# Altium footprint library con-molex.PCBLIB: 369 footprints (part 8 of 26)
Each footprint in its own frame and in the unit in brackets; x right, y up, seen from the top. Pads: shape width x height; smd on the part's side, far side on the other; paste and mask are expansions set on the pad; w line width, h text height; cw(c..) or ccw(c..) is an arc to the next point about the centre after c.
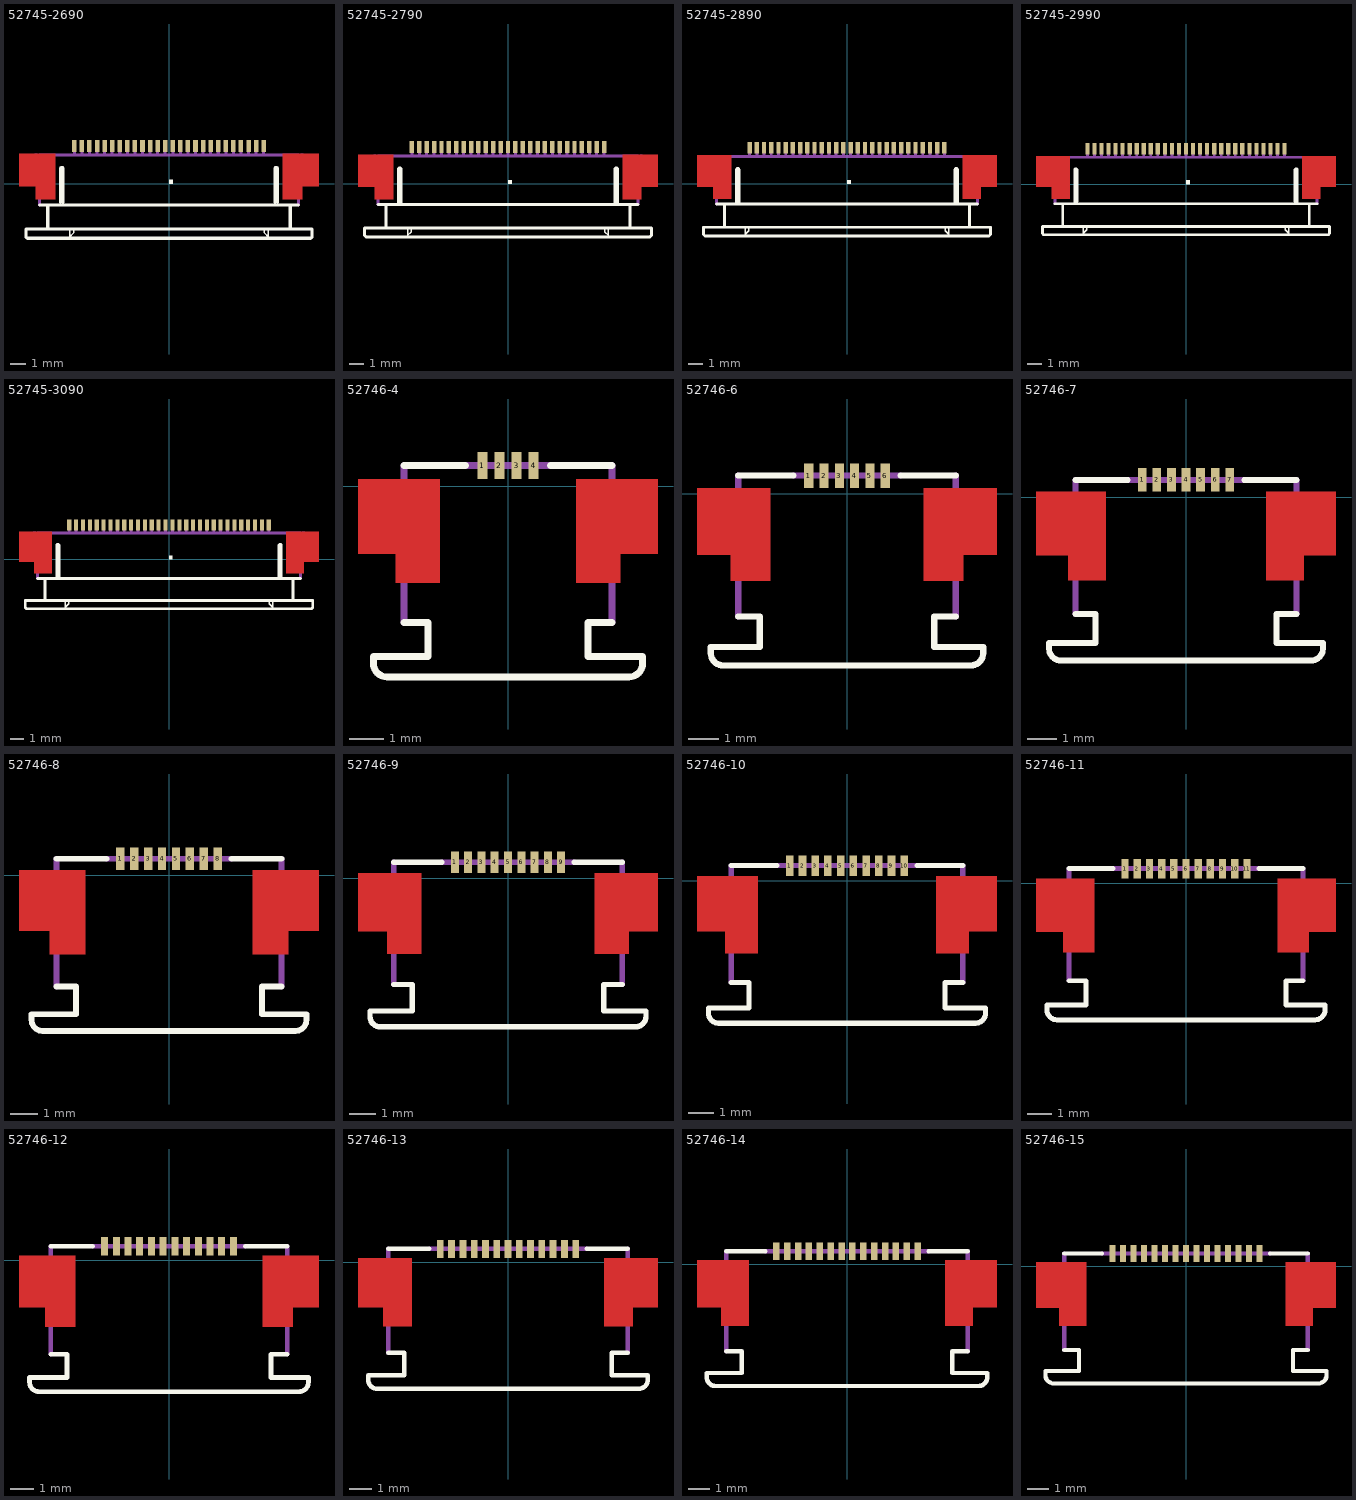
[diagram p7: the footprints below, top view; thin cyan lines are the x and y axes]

## 52745-2690 [mil]
pads (26):
  rect 11.81x31.5 smd: 1(-246.06,98.43) 2(-226.38,98.43) 3(-206.69,98.43) 4(-187.01,98.43) 5(-167.32,98.43) 6(-147.64,98.43) 7(-127.95,98.43) 8(-108.27,98.43) 9(-88.58,98.43) 10(-68.9,98.43) 11(-49.21,98.43) 12(-29.53,98.43) 13(-9.84,98.43) 14(9.84,98.43) 15(29.53,98.43) 16(49.21,98.43) 17(68.9,98.43) 18(88.58,98.43) 19(108.27,98.43) 20(127.95,98.43) 21(147.64,98.43) 22(167.32,98.43) 23(187.01,98.43) 24(206.69,98.43) 25(226.38,98.43) 26(246.06,98.43)
Top Layer:
  rectangle: -389.76,-7.87 -295.28,78.74
  rectangle: -346.46,-41.34 -295.28,-7.87
  rectangle: 295.28,-41.34 346.46,-7.87
  rectangle: 295.28,-7.87 389.76,78.74
Top Overlay:
  region: 0,0 10,0 10,10 0,10
  lines w4: -257.87,-122.05 -257.87,-137.8 -248.03,-127.95 -248.03,-122.05 ; 248.03,-122.05 248.03,-127.95 257.87,-137.8 257.87,-122.05
  lines w8: -336.61,-55.12 336.61,-55.12 ; -314.96,-114.17 -314.96,-59.06 ; -281.5,-49.21 -281.5,39.37 cw(c-278.55,39.37) -275.59,39.37 -275.59,-49.21 ; 275.59,-49.21 275.59,39.37 cw(c278.55,39.37) 281.5,39.37 281.5,-49.21 ; 314.96,-114.17 314.96,-59.06 ; -372.05,-137.8 -372.05,-118.11 372.05,-118.11 372.05,-137.8 368.11,-141.73 -368.11,-141.73 -372.05,-137.8
Top Paste:
  region: 381.89,72.83 303.15,72.83 303.15,-1.97 381.89,-1.97
  rectangle: -381.89,-1.97 -303.15,72.83
Top Solder:
  region: 389.76,78.74 344.49,78.74 344.49,-7.87 389.76,-7.87
  region: 346.46,78.74 295.28,78.74 295.28,-41.34 346.46,-41.34
  rectangle: -389.76,-7.87 -344.49,78.74
  rectangle: -346.46,-41.34 -295.28,78.74
Mechanical 16:
  rectangle: -250,78.74 -242.13,106.3
  rectangle: -230.32,78.74 -222.44,106.3
  rectangle: -210.63,78.74 -202.76,106.3
  rectangle: -190.94,78.74 -183.07,106.3
  rectangle: -171.26,78.74 -163.39,106.3
  rectangle: -151.57,78.74 -143.7,106.3
  rectangle: -131.89,78.74 -124.02,106.3
  rectangle: -112.2,78.74 -104.33,106.3
  rectangle: -92.52,78.74 -84.65,106.3
  rectangle: -72.83,78.74 -64.96,106.3
  rectangle: -53.15,78.74 -45.28,106.3
  rectangle: -33.46,78.74 -25.59,106.3
  rectangle: -13.78,78.74 -5.91,106.3
  rectangle: 5.91,78.74 13.78,106.3
  rectangle: 25.59,78.74 33.46,106.3
  rectangle: 45.28,78.74 53.15,106.3
  rectangle: 64.96,78.74 72.83,106.3
  rectangle: 84.65,78.74 92.52,106.3
  rectangle: 104.33,78.74 112.2,106.3
  rectangle: 124.02,78.74 131.89,106.3
  rectangle: 143.7,78.74 151.57,106.3
  rectangle: 163.39,78.74 171.26,106.3
  rectangle: 183.07,78.74 190.94,106.3
  rectangle: 202.76,78.74 210.63,106.3
  rectangle: 222.44,78.74 230.32,106.3
  rectangle: 242.13,78.74 250,106.3
  lines w4: -342.52,74.8 -342.52,27.56 -372.05,27.56 -372.05,35.43 -350.39,35.43 -348.43,37.4 -348.43,57.09 -372.05,57.09 -372.05,64.96 -348.43,64.96 -348.43,76.77 -342.52,76.77 ; 342.52,74.8 342.52,27.56 372.05,27.56 372.05,35.43 350.39,35.43 348.43,37.4 348.43,57.09 372.05,57.09 372.05,64.96 348.43,64.96 348.43,76.77 342.52,76.77
  lines w8: -336.61,-55.12 -336.61,74.8 336.61,74.8 336.61,-55.12

## 52745-2790 [mil]
pads (27):
  rect 11.81x31.5 smd: 1(-255.91,98.43) 2(-236.22,98.43) 3(-216.54,98.43) 4(-196.85,98.43) 5(-177.17,98.43) 6(-157.48,98.43) 7(-137.8,98.43) 8(-118.11,98.43) 9(-98.43,98.43) 10(-78.74,98.43) 11(-59.06,98.43) 12(-39.37,98.43) 13(-19.69,98.43) 14(0,98.43) 15(19.69,98.43) 16(39.37,98.43) 17(59.06,98.43) 18(78.74,98.43) 19(98.43,98.43) 20(118.11,98.43) 21(137.8,98.43) 22(157.48,98.43) 23(177.17,98.43) 24(196.85,98.43) 25(216.54,98.43) 26(236.22,98.43) 27(255.91,98.43)
Top Layer:
  rectangle: -399.61,-7.87 -305.12,78.74
  rectangle: -356.3,-41.34 -305.12,-7.87
  rectangle: 305.12,-41.34 356.3,-7.87
  rectangle: 305.12,-7.87 399.61,78.74
Top Overlay:
  region: 0,0 10,0 10,10 0,10
  lines w4: -267.72,-122.05 -267.72,-137.8 -257.87,-127.95 -257.87,-122.05 ; 257.87,-122.05 257.87,-127.95 267.72,-137.8 267.72,-122.05
  lines w8: -346.46,-55.12 346.46,-55.12 ; -324.8,-114.17 -324.8,-59.06 ; -291.34,-49.21 -291.34,39.37 cw(c-288.38,39.37) -285.43,39.37 -285.43,-49.21 ; 285.43,-49.21 285.43,39.37 cw(c288.38,39.37) 291.34,39.37 291.34,-49.21 ; 324.8,-114.17 324.8,-59.06 ; -381.89,-137.8 -381.89,-118.11 381.89,-118.11 381.89,-137.8 377.95,-141.73 -377.95,-141.73 -381.89,-137.8
Top Paste:
  region: 391.73,72.83 312.99,72.83 312.99,-1.97 391.73,-1.97
  rectangle: -391.73,-1.97 -312.99,72.83
Top Solder:
  region: 399.61,78.74 354.33,78.74 354.33,-7.87 399.61,-7.87
  region: 356.3,78.74 305.12,78.74 305.12,-41.34 356.3,-41.34
  rectangle: -399.61,-7.87 -354.33,78.74
  rectangle: -356.3,-41.34 -305.12,78.74
Mechanical 16:
  rectangle: -259.84,78.74 -251.97,106.3
  rectangle: -240.16,78.74 -232.28,106.3
  rectangle: -220.47,78.74 -212.6,106.3
  rectangle: -200.79,78.74 -192.91,106.3
  rectangle: -181.1,78.74 -173.23,106.3
  rectangle: -161.42,78.74 -153.54,106.3
  rectangle: -141.73,78.74 -133.86,106.3
  rectangle: -122.05,78.74 -114.17,106.3
  rectangle: -102.36,78.74 -94.49,106.3
  rectangle: -82.68,78.74 -74.8,106.3
  rectangle: -62.99,78.74 -55.12,106.3
  rectangle: -43.31,78.74 -35.43,106.3
  rectangle: -23.62,78.74 -15.75,106.3
  rectangle: -3.94,78.74 3.94,106.3
  rectangle: 15.75,78.74 23.62,106.3
  rectangle: 35.43,78.74 43.31,106.3
  rectangle: 55.12,78.74 62.99,106.3
  rectangle: 74.8,78.74 82.68,106.3
  rectangle: 94.49,78.74 102.36,106.3
  rectangle: 114.17,78.74 122.05,106.3
  rectangle: 133.86,78.74 141.73,106.3
  rectangle: 153.54,78.74 161.42,106.3
  rectangle: 173.23,78.74 181.1,106.3
  rectangle: 192.91,78.74 200.79,106.3
  rectangle: 212.6,78.74 220.47,106.3
  rectangle: 232.28,78.74 240.16,106.3
  rectangle: 251.97,78.74 259.84,106.3
  lines w4: -352.36,74.8 -352.36,27.56 -381.89,27.56 -381.89,35.43 -360.24,35.43 -358.27,37.4 -358.27,57.09 -381.89,57.09 -381.89,64.96 -358.27,64.96 -358.27,76.77 -352.36,76.77 ; 352.36,74.8 352.36,27.56 381.89,27.56 381.89,35.43 360.24,35.43 358.27,37.4 358.27,57.09 381.89,57.09 381.89,64.96 358.27,64.96 358.27,76.77 352.36,76.77
  lines w8: -346.46,-55.12 -346.46,74.8 346.46,74.8 346.46,-55.12

## 52745-2890 [mil]
pads (28):
  rect 11.81x31.5 smd: 1(-265.75,98.43) 2(-246.06,98.43) 3(-226.38,98.43) 4(-206.69,98.43) 5(-187.01,98.43) 6(-167.32,98.43) 7(-147.64,98.43) 8(-127.95,98.43) 9(-108.27,98.43) 10(-88.58,98.43) 11(-68.9,98.43) 12(-49.21,98.43) 13(-29.53,98.43) 14(-9.84,98.43) 15(9.84,98.43) 16(29.53,98.43) 17(49.21,98.43) 18(68.9,98.43) 19(88.58,98.43) 20(108.27,98.43) 21(127.95,98.43) 22(147.64,98.43) 23(167.32,98.43) 24(187.01,98.43) 25(206.69,98.43) 26(226.38,98.43) 27(246.06,98.43) 28(265.75,98.43)
Top Layer:
  rectangle: -409.45,-7.87 -314.96,78.74
  rectangle: -366.14,-41.34 -314.96,-7.87
  rectangle: 314.96,-41.34 366.14,-7.87
  rectangle: 314.96,-7.87 409.45,78.74
Top Overlay:
  region: 0,0 10,0 10,10 0,10
  lines w4: -277.56,-122.05 -277.56,-137.8 -267.72,-127.95 -267.72,-122.05 ; 267.72,-122.05 267.72,-127.95 277.56,-137.8 277.56,-122.05
  lines w8: -356.3,-55.12 356.3,-55.12 ; -334.65,-114.17 -334.65,-59.06 ; -301.18,-49.21 -301.18,39.37 cw(c-298.23,39.37) -295.28,39.37 -295.28,-49.21 ; 295.28,-49.21 295.28,39.37 cw(c298.23,39.37) 301.18,39.37 301.18,-49.21 ; 334.65,-114.17 334.65,-59.06 ; -391.73,-137.8 -391.73,-118.11 391.73,-118.11 391.73,-137.8 387.8,-141.73 -387.8,-141.73 -391.73,-137.8
Top Paste:
  region: 401.57,72.83 322.83,72.83 322.83,-1.97 401.57,-1.97
  rectangle: -401.57,-1.97 -322.83,72.83
Top Solder:
  region: 409.45,78.74 364.17,78.74 364.17,-7.87 409.45,-7.87
  region: 366.14,78.74 314.96,78.74 314.96,-41.34 366.14,-41.34
  rectangle: -409.45,-7.87 -364.17,78.74
  rectangle: -366.14,-41.34 -314.96,78.74
Mechanical 16:
  rectangle: -269.69,78.74 -261.81,106.3
  rectangle: -250,78.74 -242.13,106.3
  rectangle: -230.32,78.74 -222.44,106.3
  rectangle: -210.63,78.74 -202.76,106.3
  rectangle: -190.94,78.74 -183.07,106.3
  rectangle: -171.26,78.74 -163.39,106.3
  rectangle: -151.57,78.74 -143.7,106.3
  rectangle: -131.89,78.74 -124.02,106.3
  rectangle: -112.2,78.74 -104.33,106.3
  rectangle: -92.52,78.74 -84.65,106.3
  rectangle: -72.83,78.74 -64.96,106.3
  rectangle: -53.15,78.74 -45.28,106.3
  rectangle: -33.46,78.74 -25.59,106.3
  rectangle: -13.78,78.74 -5.91,106.3
  rectangle: 5.91,78.74 13.78,106.3
  rectangle: 25.59,78.74 33.46,106.3
  rectangle: 45.28,78.74 53.15,106.3
  rectangle: 64.96,78.74 72.83,106.3
  rectangle: 84.65,78.74 92.52,106.3
  rectangle: 104.33,78.74 112.2,106.3
  rectangle: 124.02,78.74 131.89,106.3
  rectangle: 143.7,78.74 151.57,106.3
  rectangle: 163.39,78.74 171.26,106.3
  rectangle: 183.07,78.74 190.94,106.3
  rectangle: 202.76,78.74 210.63,106.3
  rectangle: 222.44,78.74 230.32,106.3
  rectangle: 242.13,78.74 250,106.3
  rectangle: 261.81,78.74 269.69,106.3
  lines w4: -362.2,74.8 -362.2,27.56 -391.73,27.56 -391.73,35.43 -370.08,35.43 -368.11,37.4 -368.11,57.09 -391.73,57.09 -391.73,64.96 -368.11,64.96 -368.11,76.77 -362.2,76.77 ; 362.2,74.8 362.2,27.56 391.73,27.56 391.73,35.43 370.08,35.43 368.11,37.4 368.11,57.09 391.73,57.09 391.73,64.96 368.11,64.96 368.11,76.77 362.2,76.77
  lines w8: -356.3,-55.12 -356.3,74.8 356.3,74.8 356.3,-55.12

## 52745-2990 [mil]
pads (29):
  rect 11.81x31.5 smd: 1(-275.59,98.43) 2(-255.91,98.43) 3(-236.22,98.43) 4(-216.54,98.43) 5(-196.85,98.43) 6(-177.17,98.43) 7(-157.48,98.43) 8(-137.8,98.43) 9(-118.11,98.43) 10(-98.43,98.43) 11(-78.74,98.43) 12(-59.06,98.43) 13(-39.37,98.43) 14(-19.69,98.43) 15(0,98.43) 16(19.69,98.43) 17(39.37,98.43) 18(59.06,98.43) 19(78.74,98.43) 20(98.43,98.43) 21(118.11,98.43) 22(137.8,98.43) 23(157.48,98.43) 24(177.17,98.43) 25(196.85,98.43) 26(216.54,98.43) 27(236.22,98.43) 28(255.91,98.43) 29(275.59,98.43)
Top Layer:
  rectangle: -419.29,-7.87 -324.8,78.74
  rectangle: -375.98,-41.34 -324.8,-7.87
  rectangle: 324.8,-41.34 375.98,-7.87
  rectangle: 324.8,-7.87 419.29,78.74
Top Overlay:
  region: 0,0 10,0 10,10 0,10
  lines w4: -287.4,-122.05 -287.4,-137.8 -277.56,-127.95 -277.56,-122.05 ; 277.56,-122.05 277.56,-127.95 287.4,-137.8 287.4,-122.05
  lines w8: -366.14,-55.12 366.14,-55.12 ; -344.49,-114.17 -344.49,-59.06 ; -311.02,-49.21 -311.02,39.37 cw(c-308.07,39.37) -305.12,39.37 -305.12,-49.21 ; 305.12,-49.21 305.12,39.37 cw(c308.07,39.37) 311.02,39.37 311.02,-49.21 ; 344.49,-114.17 344.49,-59.06 ; -401.57,-137.8 -401.57,-118.11 401.57,-118.11 401.57,-137.8 397.64,-141.73 -397.64,-141.73 -401.57,-137.8
Top Paste:
  region: 411.42,72.83 332.68,72.83 332.68,-1.97 411.42,-1.97
  rectangle: -411.42,-1.97 -332.68,72.83
Top Solder:
  region: 419.29,78.74 374.02,78.74 374.02,-7.87 419.29,-7.87
  region: 375.98,78.74 324.8,78.74 324.8,-41.34 375.98,-41.34
  rectangle: -419.29,-7.87 -374.02,78.74
  rectangle: -375.98,-41.34 -324.8,78.74
Mechanical 16:
  rectangle: -279.53,78.74 -271.65,106.3
  rectangle: -259.84,78.74 -251.97,106.3
  rectangle: -240.16,78.74 -232.28,106.3
  rectangle: -220.47,78.74 -212.6,106.3
  rectangle: -200.79,78.74 -192.91,106.3
  rectangle: -181.1,78.74 -173.23,106.3
  rectangle: -161.42,78.74 -153.54,106.3
  rectangle: -141.73,78.74 -133.86,106.3
  rectangle: -122.05,78.74 -114.17,106.3
  rectangle: -102.36,78.74 -94.49,106.3
  rectangle: -82.68,78.74 -74.8,106.3
  rectangle: -62.99,78.74 -55.12,106.3
  rectangle: -43.31,78.74 -35.43,106.3
  rectangle: -23.62,78.74 -15.75,106.3
  rectangle: -3.94,78.74 3.94,106.3
  rectangle: 15.75,78.74 23.62,106.3
  rectangle: 35.43,78.74 43.31,106.3
  rectangle: 55.12,78.74 62.99,106.3
  rectangle: 74.8,78.74 82.68,106.3
  rectangle: 94.49,78.74 102.36,106.3
  rectangle: 114.17,78.74 122.05,106.3
  rectangle: 133.86,78.74 141.73,106.3
  rectangle: 153.54,78.74 161.42,106.3
  rectangle: 173.23,78.74 181.1,106.3
  rectangle: 192.91,78.74 200.79,106.3
  rectangle: 212.6,78.74 220.47,106.3
  rectangle: 232.28,78.74 240.16,106.3
  rectangle: 251.97,78.74 259.84,106.3
  rectangle: 271.65,78.74 279.53,106.3
  lines w4: -372.05,74.8 -372.05,27.56 -401.57,27.56 -401.57,35.43 -379.92,35.43 -377.95,37.4 -377.95,57.09 -401.57,57.09 -401.57,64.96 -377.95,64.96 -377.95,76.77 -372.05,76.77 ; 372.05,74.8 372.05,27.56 401.57,27.56 401.57,35.43 379.92,35.43 377.95,37.4 377.95,57.09 401.57,57.09 401.57,64.96 377.95,64.96 377.95,76.77 372.05,76.77
  lines w8: -366.14,-55.12 -366.14,74.8 366.14,74.8 366.14,-55.12

## 52745-3090 [mil]
pads (30):
  rect 11.81x31.5 smd: 1(-285.43,98.43) 2(-265.75,98.43) 3(-246.06,98.43) 4(-226.38,98.43) 5(-206.69,98.43) 6(-187.01,98.43) 7(-167.32,98.43) 8(-147.64,98.43) 9(-127.95,98.43) 10(-108.27,98.43) 11(-88.58,98.43) 12(-68.9,98.43) 13(-49.21,98.43) 14(-29.53,98.43) 15(-9.84,98.43) 16(9.84,98.43) 17(29.53,98.43) 18(49.21,98.43) 19(68.9,98.43) 20(88.58,98.43) 21(108.27,98.43) 22(127.95,98.43) 23(147.64,98.43) 24(167.32,98.43) 25(187.01,98.43) 26(206.69,98.43) 27(226.38,98.43) 28(246.06,98.43) 29(265.75,98.43) 30(285.43,98.43)
Top Layer:
  rectangle: -429.13,-7.87 -334.65,78.74
  rectangle: -385.83,-41.34 -334.65,-7.87
  rectangle: 334.65,-41.34 385.83,-7.87
  rectangle: 334.65,-7.87 429.13,78.74
Top Overlay:
  region: 0,0 10,0 10,10 0,10
  lines w4: -297.24,-122.05 -297.24,-137.8 -287.4,-127.95 -287.4,-122.05 ; 287.4,-122.05 287.4,-127.95 297.24,-137.8 297.24,-122.05
  lines w8: -375.98,-55.12 375.98,-55.12 ; -354.33,-114.17 -354.33,-59.06 ; -320.87,-49.21 -320.87,39.37 cw(c-317.92,39.37) -314.96,39.37 -314.96,-49.21 ; 314.96,-49.21 314.96,39.37 cw(c317.92,39.37) 320.87,39.37 320.87,-49.21 ; 354.33,-114.17 354.33,-59.06 ; -411.42,-137.8 -411.42,-118.11 411.42,-118.11 411.42,-137.8 407.48,-141.73 -407.48,-141.73 -411.42,-137.8
Top Paste:
  region: 421.26,72.83 342.52,72.83 342.52,-1.97 421.26,-1.97
  rectangle: -421.26,-1.97 -342.52,72.83
Top Solder:
  region: 429.13,78.74 383.86,78.74 383.86,-7.87 429.13,-7.87
  region: 385.83,78.74 334.65,78.74 334.65,-41.34 385.83,-41.34
  rectangle: -429.13,-7.87 -383.86,78.74
  rectangle: -385.83,-41.34 -334.65,78.74
Mechanical 16:
  rectangle: -289.37,78.74 -281.5,106.3
  rectangle: -269.69,78.74 -261.81,106.3
  rectangle: -250,78.74 -242.13,106.3
  rectangle: -230.32,78.74 -222.44,106.3
  rectangle: -210.63,78.74 -202.76,106.3
  rectangle: -190.94,78.74 -183.07,106.3
  rectangle: -171.26,78.74 -163.39,106.3
  rectangle: -151.57,78.74 -143.7,106.3
  rectangle: -131.89,78.74 -124.02,106.3
  rectangle: -112.2,78.74 -104.33,106.3
  rectangle: -92.52,78.74 -84.65,106.3
  rectangle: -72.83,78.74 -64.96,106.3
  rectangle: -53.15,78.74 -45.28,106.3
  rectangle: -33.46,78.74 -25.59,106.3
  rectangle: -13.78,78.74 -5.91,106.3
  rectangle: 5.91,78.74 13.78,106.3
  rectangle: 25.59,78.74 33.46,106.3
  rectangle: 45.28,78.74 53.15,106.3
  rectangle: 64.96,78.74 72.83,106.3
  rectangle: 84.65,78.74 92.52,106.3
  rectangle: 104.33,78.74 112.2,106.3
  rectangle: 124.02,78.74 131.89,106.3
  rectangle: 143.7,78.74 151.57,106.3
  rectangle: 163.39,78.74 171.26,106.3
  rectangle: 183.07,78.74 190.94,106.3
  rectangle: 202.76,78.74 210.63,106.3
  rectangle: 222.44,78.74 230.32,106.3
  rectangle: 242.13,78.74 250,106.3
  rectangle: 261.81,78.74 269.69,106.3
  rectangle: 281.5,78.74 289.37,106.3
  lines w4: -381.89,74.8 -381.89,27.56 -411.42,27.56 -411.42,35.43 -389.76,35.43 -387.8,37.4 -387.8,57.09 -411.42,57.09 -411.42,64.96 -387.8,64.96 -387.8,76.77 -381.89,76.77 ; 381.89,74.8 381.89,27.56 411.42,27.56 411.42,35.43 389.76,35.43 387.8,37.4 387.8,57.09 411.42,57.09 411.42,64.96 387.8,64.96 387.8,76.77 381.89,76.77
  lines w8: -375.98,-55.12 -375.98,74.8 375.98,74.8 375.98,-55.12

## 52746-4 [mil]
pads (4):
  rect 11.81x31.5 smd: 1(-29.53,23.62) 2(-9.84,23.62) 3(9.84,23.62) 4(29.53,23.62)
Top Layer:
  rectangle: -173.23,-78.74 -78.74,7.87
  rectangle: -129.92,-112.2 -78.74,-78.74
  rectangle: 78.74,-78.74 173.23,7.87
  rectangle: 78.74,-112.2 129.92,-78.74
Top Overlay:
  lines w8: -120.08,-157.48 -92.52,-157.48 -92.52,-196.85 -155.51,-196.85 -155.51,-204.72 ccw(c-139.76,-204.72) -139.76,-220.47 139.76,-220.47 ccw(c139.76,-204.72) 155.51,-204.72 155.51,-196.85 92.52,-196.85 92.52,-157.48 120.08,-157.48 ; -120.08,23.62 -49.21,23.62 ; 49.21,23.62 120.08,23.62
Top Paste:
  rectangle: -168.31,-74.8 -82.68,2.95
  rectangle: -125.98,-108.27 -82.68,-74.8
  rectangle: 82.68,-74.8 168.31,2.95
  rectangle: 82.68,-108.27 125.98,-74.8
Top Solder:
  rectangle: -173.23,-78.74 -78.74,7.87
  rectangle: -129.92,-112.2 -78.74,-78.74
  rectangle: 78.74,-78.74 173.23,7.87
  rectangle: 78.74,-112.2 129.92,-78.74
  rectangle: -36.42,6.89 -22.64,40.35
  rectangle: -16.73,6.89 -2.95,40.35
  rectangle: 2.95,6.89 16.73,40.35
  rectangle: 22.64,6.89 36.42,40.35
Mechanical 16:
  lines w8: -120.08,-157.48 -120.08,23.62 ; -49.21,23.62 49.21,23.62 ; 120.08,-157.48 120.08,23.62
  lines w19.69: -157.48,-55.12 -125.98,-55.12 -125.98,-9.84 -157.48,-9.84 ; 157.48,-55.12 125.98,-55.12 125.98,-9.84 157.48,-9.84

## 52746-6 [mil]
pads (6):
  rect 11.81x31.5 smd: 1(-49.21,23.62) 2(-29.53,23.62) 3(-9.84,23.62) 4(9.84,23.62) 5(29.53,23.62) 6(49.21,23.62)
Top Layer:
  rectangle: -192.91,-78.74 -98.43,7.87
  rectangle: -149.61,-112.2 -98.43,-78.74
  rectangle: 98.43,-78.74 192.91,7.87
  rectangle: 98.43,-112.2 149.61,-78.74
Top Overlay:
  lines w8: -139.76,-157.48 -112.2,-157.48 -112.2,-196.85 -175.2,-196.85 -175.2,-204.72 ccw(c-159.45,-204.72) -159.45,-220.47 159.45,-220.47 ccw(c159.45,-204.72) 175.2,-204.72 175.2,-196.85 112.2,-196.85 112.2,-157.48 139.76,-157.48 ; -139.76,23.62 -68.9,23.62 ; 68.9,23.62 139.76,23.62
Top Paste:
  rectangle: -187.99,-74.8 -102.36,2.95
  rectangle: -145.67,-108.27 -102.36,-74.8
  rectangle: 102.36,-74.8 187.99,2.95
  rectangle: 102.36,-108.27 145.67,-74.8
Top Solder:
  rectangle: -192.91,-78.74 -98.43,7.87
  rectangle: -149.61,-112.2 -98.43,-78.74
  rectangle: 98.43,-78.74 192.91,7.87
  rectangle: 98.43,-112.2 149.61,-78.74
  rectangle: -56.1,6.89 -42.32,40.35
  rectangle: -36.42,6.89 -22.64,40.35
  rectangle: -16.73,6.89 -2.95,40.35
  rectangle: 2.95,6.89 16.73,40.35
  rectangle: 22.64,6.89 36.42,40.35
  rectangle: 42.32,6.89 56.1,40.35
Mechanical 16:
  lines w8: -139.76,-157.48 -139.76,23.62 ; -68.9,23.62 68.9,23.62 ; 139.76,-157.48 139.76,23.62
  lines w19.69: -177.17,-55.12 -145.67,-55.12 -145.67,-9.84 -177.17,-9.84 ; 177.17,-55.12 145.67,-55.12 145.67,-9.84 177.17,-9.84

## 52746-7 [mil]
pads (7):
  rect 11.81x31.5 smd: 1(-59.06,23.62) 2(-39.37,23.62) 3(-19.69,23.62) 4(0,23.62) 5(19.69,23.62) 6(39.37,23.62) 7(59.06,23.62)
Top Layer:
  rectangle: -202.76,-78.74 -108.27,7.87
  rectangle: -159.45,-112.2 -108.27,-78.74
  rectangle: 108.27,-78.74 202.76,7.87
  rectangle: 108.27,-112.2 159.45,-78.74
Top Overlay:
  lines w8: -149.61,-157.48 -122.05,-157.48 -122.05,-196.85 -185.04,-196.85 -185.04,-204.72 ccw(c-169.29,-204.72) -169.29,-220.47 169.29,-220.47 ccw(c169.29,-204.72) 185.04,-204.72 185.04,-196.85 122.05,-196.85 122.05,-157.48 149.61,-157.48 ; -149.61,23.62 -78.74,23.62 ; 78.74,23.62 149.61,23.62
Top Paste:
  rectangle: -197.83,-74.8 -112.2,2.95
  rectangle: -155.51,-108.27 -112.2,-74.8
  rectangle: 112.2,-74.8 197.83,2.95
  rectangle: 112.2,-108.27 155.51,-74.8
Top Solder:
  rectangle: -202.76,-78.74 -108.27,7.87
  rectangle: -159.45,-112.2 -108.27,-78.74
  rectangle: 108.27,-78.74 202.76,7.87
  rectangle: 108.27,-112.2 159.45,-78.74
  rectangle: -65.94,6.89 -52.17,40.35
  rectangle: -46.26,6.89 -32.48,40.35
  rectangle: -26.57,6.89 -12.8,40.35
  rectangle: -6.89,6.89 6.89,40.35
  rectangle: 12.8,6.89 26.57,40.35
  rectangle: 32.48,6.89 46.26,40.35
  rectangle: 52.17,6.89 65.94,40.35
Mechanical 16:
  lines w8: -149.61,-157.48 -149.61,23.62 ; -78.74,23.62 78.74,23.62 ; 149.61,-157.48 149.61,23.62
  lines w19.69: -187.01,-55.12 -155.51,-55.12 -155.51,-9.84 -187.01,-9.84 ; 187.01,-55.12 155.51,-55.12 155.51,-9.84 187.01,-9.84

## 52746-8 [mil]
pads (8):
  rect 11.81x31.5 smd: 1(-68.9,23.62) 2(-49.21,23.62) 3(-29.53,23.62) 4(-9.84,23.62) 5(9.84,23.62) 6(29.53,23.62) 7(49.21,23.62) 8(68.9,23.62)
Top Layer:
  rectangle: -212.6,-78.74 -118.11,7.87
  rectangle: -169.29,-112.2 -118.11,-78.74
  rectangle: 118.11,-78.74 212.6,7.87
  rectangle: 118.11,-112.2 169.29,-78.74
Top Overlay:
  lines w8: -159.45,-157.48 -131.89,-157.48 -131.89,-196.85 -194.88,-196.85 -194.88,-204.72 ccw(c-179.13,-204.72) -179.13,-220.47 179.13,-220.47 ccw(c179.13,-204.72) 194.88,-204.72 194.88,-196.85 131.89,-196.85 131.89,-157.48 159.45,-157.48 ; -159.45,23.62 -88.58,23.62 ; 88.58,23.62 159.45,23.62
Top Paste:
  rectangle: -207.68,-74.8 -122.05,2.95
  rectangle: -165.35,-108.27 -122.05,-74.8
  rectangle: 122.05,-74.8 207.68,2.95
  rectangle: 122.05,-108.27 165.35,-74.8
Top Solder:
  rectangle: -212.6,-78.74 -118.11,7.87
  rectangle: -169.29,-112.2 -118.11,-78.74
  rectangle: 118.11,-78.74 212.6,7.87
  rectangle: 118.11,-112.2 169.29,-78.74
  rectangle: -75.79,6.89 -62.01,40.35
  rectangle: -56.1,6.89 -42.32,40.35
  rectangle: -36.42,6.89 -22.64,40.35
  rectangle: -16.73,6.89 -2.95,40.35
  rectangle: 2.95,6.89 16.73,40.35
  rectangle: 22.64,6.89 36.42,40.35
  rectangle: 42.32,6.89 56.1,40.35
  rectangle: 62.01,6.89 75.79,40.35
Mechanical 16:
  lines w8: -159.45,-157.48 -159.45,23.62 ; -88.58,23.62 88.58,23.62 ; 159.45,-157.48 159.45,23.62
  lines w19.69: -196.85,-55.12 -165.35,-55.12 -165.35,-9.84 -196.85,-9.84 ; 196.85,-55.12 165.35,-55.12 165.35,-9.84 196.85,-9.84

## 52746-9 [mil]
pads (9):
  rect 11.81x31.5 smd: 1(-78.74,23.62) 2(-59.06,23.62) 3(-39.37,23.62) 4(-19.69,23.62) 5(0,23.62) 6(19.69,23.62) 7(39.37,23.62) 8(59.06,23.62) 9(78.74,23.62)
Top Layer:
  rectangle: -222.44,-78.74 -127.95,7.87
  rectangle: -179.13,-112.2 -127.95,-78.74
  rectangle: 127.95,-78.74 222.44,7.87
  rectangle: 127.95,-112.2 179.13,-78.74
Top Overlay:
  lines w8: -169.29,-157.48 -141.73,-157.48 -141.73,-196.85 -204.72,-196.85 -204.72,-204.72 ccw(c-188.97,-204.72) -188.98,-220.47 188.98,-220.47 ccw(c188.97,-204.72) 204.72,-204.72 204.72,-196.85 141.73,-196.85 141.73,-157.48 169.29,-157.48 ; -169.29,23.62 -98.43,23.62 ; 98.43,23.62 169.29,23.62
Top Paste:
  rectangle: -217.52,-74.8 -131.89,2.95
  rectangle: -175.2,-108.27 -131.89,-74.8
  rectangle: 131.89,-74.8 217.52,2.95
  rectangle: 131.89,-108.27 175.2,-74.8
Top Solder:
  rectangle: -222.44,-78.74 -127.95,7.87
  rectangle: -179.13,-112.2 -127.95,-78.74
  rectangle: 127.95,-78.74 222.44,7.87
  rectangle: 127.95,-112.2 179.13,-78.74
  rectangle: -85.63,6.89 -71.85,40.35
  rectangle: -65.94,6.89 -52.17,40.35
  rectangle: -46.26,6.89 -32.48,40.35
  rectangle: -26.57,6.89 -12.8,40.35
  rectangle: -6.89,6.89 6.89,40.35
  rectangle: 12.8,6.89 26.57,40.35
  rectangle: 32.48,6.89 46.26,40.35
  rectangle: 52.17,6.89 65.94,40.35
  rectangle: 71.85,6.89 85.63,40.35
Mechanical 16:
  lines w8: -169.29,-157.48 -169.29,23.62 ; -98.43,23.62 98.43,23.62 ; 169.29,-157.48 169.29,23.62
  lines w19.69: -206.69,-55.12 -175.2,-55.12 -175.2,-9.84 -206.69,-9.84 ; 206.69,-55.12 175.2,-55.12 175.2,-9.84 206.69,-9.84

## 52746-10 [mil]
pads (10):
  rect 11.81x31.5 smd: 1(-88.58,23.62) 2(-68.9,23.62) 3(-49.21,23.62) 4(-29.53,23.62) 5(-9.84,23.62) 6(9.84,23.62) 7(29.53,23.62) 8(49.21,23.62) 9(68.9,23.62) 10(88.58,23.62)
Top Layer:
  rectangle: -232.28,-78.74 -137.8,7.87
  rectangle: -188.98,-112.2 -137.8,-78.74
  rectangle: 137.8,-78.74 232.28,7.87
  rectangle: 137.8,-112.2 188.98,-78.74
Top Overlay:
  lines w8: -179.13,-157.48 -151.57,-157.48 -151.57,-196.85 -214.57,-196.85 -214.57,-204.72 ccw(c-198.82,-204.72) -198.82,-220.47 198.82,-220.47 ccw(c198.82,-204.72) 214.57,-204.72 214.57,-196.85 151.57,-196.85 151.57,-157.48 179.13,-157.48 ; -179.13,23.62 -108.27,23.62 ; 108.27,23.62 179.13,23.62
Top Paste:
  rectangle: -227.36,-74.8 -141.73,2.95
  rectangle: -185.04,-108.27 -141.73,-74.8
  rectangle: 141.73,-74.8 227.36,2.95
  rectangle: 141.73,-108.27 185.04,-74.8
Top Solder:
  rectangle: -232.28,-78.74 -137.8,7.87
  rectangle: -188.98,-112.2 -137.8,-78.74
  rectangle: 137.8,-78.74 232.28,7.87
  rectangle: 137.8,-112.2 188.98,-78.74
  rectangle: -95.47,6.89 -81.69,40.35
  rectangle: -75.79,6.89 -62.01,40.35
  rectangle: -56.1,6.89 -42.32,40.35
  rectangle: -36.42,6.89 -22.64,40.35
  rectangle: -16.73,6.89 -2.95,40.35
  rectangle: 2.95,6.89 16.73,40.35
  rectangle: 22.64,6.89 36.42,40.35
  rectangle: 42.32,6.89 56.1,40.35
  rectangle: 62.01,6.89 75.79,40.35
  rectangle: 81.69,6.89 95.47,40.35
Mechanical 16:
  lines w8: -179.13,-157.48 -179.13,23.62 ; -108.27,23.62 108.27,23.62 ; 179.13,-157.48 179.13,23.62
  lines w19.69: -216.54,-55.12 -185.04,-55.12 -185.04,-9.84 -216.54,-9.84 ; 216.54,-55.12 185.04,-55.12 185.04,-9.84 216.54,-9.84

## 52746-11 [mil]
pads (11):
  rect 11.81x31.5 smd: 1(-98.43,23.62) 2(-78.74,23.62) 3(-59.06,23.62) 4(-39.37,23.62) 5(-19.69,23.62) 6(0,23.62) 7(19.69,23.62) 8(39.37,23.62) 9(59.06,23.62) 10(78.74,23.62) 11(98.43,23.62)
Top Layer:
  rectangle: -242.13,-78.74 -147.64,7.87
  rectangle: -198.82,-112.2 -147.64,-78.74
  rectangle: 147.64,-78.74 242.13,7.87
  rectangle: 147.64,-112.2 198.82,-78.74
Top Overlay:
  lines w8: -188.98,-157.48 -161.42,-157.48 -161.42,-196.85 -224.41,-196.85 -224.41,-204.72 ccw(c-208.66,-204.72) -208.66,-220.47 208.66,-220.47 ccw(c208.66,-204.72) 224.41,-204.72 224.41,-196.85 161.42,-196.85 161.42,-157.48 188.98,-157.48 ; -188.98,23.62 -118.11,23.62 ; 118.11,23.62 188.98,23.62
Top Paste:
  rectangle: -237.2,-74.8 -151.57,2.95
  rectangle: -194.88,-108.27 -151.57,-74.8
  rectangle: 151.57,-74.8 237.2,2.95
  rectangle: 151.57,-108.27 194.88,-74.8
Top Solder:
  rectangle: -242.13,-78.74 -147.64,7.87
  rectangle: -198.82,-112.2 -147.64,-78.74
  rectangle: 147.64,-78.74 242.13,7.87
  rectangle: 147.64,-112.2 198.82,-78.74
  rectangle: -105.32,6.89 -91.54,40.35
  rectangle: -85.63,6.89 -71.85,40.35
  rectangle: -65.94,6.89 -52.17,40.35
  rectangle: -46.26,6.89 -32.48,40.35
  rectangle: -26.57,6.89 -12.8,40.35
  rectangle: -6.89,6.89 6.89,40.35
  rectangle: 12.8,6.89 26.57,40.35
  rectangle: 32.48,6.89 46.26,40.35
  rectangle: 52.17,6.89 65.94,40.35
  rectangle: 71.85,6.89 85.63,40.35
  rectangle: 91.54,6.89 105.32,40.35
Mechanical 16:
  lines w8: -188.98,-157.48 -188.98,23.62 ; -118.11,23.62 118.11,23.62 ; 188.98,-157.48 188.98,23.62
  lines w19.69: -226.38,-55.12 -194.88,-55.12 -194.88,-9.84 -226.38,-9.84 ; 226.38,-55.12 194.88,-55.12 194.88,-9.84 226.38,-9.84

## 52746-12 [mil]
pads (12):
  rect 11.81x31.5 smd: 1(-108.27,23.62) 2(-88.58,23.62) 3(-68.9,23.62) 4(-49.21,23.62) 5(-29.53,23.62) 6(-9.84,23.62) 7(9.84,23.62) 8(29.53,23.62) 9(49.21,23.62) 10(68.9,23.62) 11(88.58,23.62) 12(108.27,23.62)
Top Layer:
  rectangle: -251.97,-78.74 -157.48,7.87
  rectangle: -208.66,-112.2 -157.48,-78.74
  rectangle: 157.48,-78.74 251.97,7.87
  rectangle: 157.48,-112.2 208.66,-78.74
Top Overlay:
  lines w8: -198.82,-157.48 -171.26,-157.48 -171.26,-196.85 -234.25,-196.85 -234.25,-204.72 ccw(c-218.5,-204.72) -218.5,-220.47 218.5,-220.47 ccw(c218.5,-204.72) 234.25,-204.72 234.25,-196.85 171.26,-196.85 171.26,-157.48 198.82,-157.48 ; -198.82,23.62 -127.95,23.62 ; 127.95,23.62 198.82,23.62
Top Paste:
  rectangle: -247.05,-74.8 -161.42,2.95
  rectangle: -204.72,-108.27 -161.42,-74.8
  rectangle: 161.42,-74.8 247.05,2.95
  rectangle: 161.42,-108.27 204.72,-74.8
Top Solder:
  rectangle: -251.97,-78.74 -157.48,7.87
  rectangle: -208.66,-112.2 -157.48,-78.74
  rectangle: 157.48,-78.74 251.97,7.87
  rectangle: 157.48,-112.2 208.66,-78.74
  rectangle: -115.16,6.89 -101.38,40.35
  rectangle: -95.47,6.89 -81.69,40.35
  rectangle: -75.79,6.89 -62.01,40.35
  rectangle: -56.1,6.89 -42.32,40.35
  rectangle: -36.42,6.89 -22.64,40.35
  rectangle: -16.73,6.89 -2.95,40.35
  rectangle: 2.95,6.89 16.73,40.35
  rectangle: 22.64,6.89 36.42,40.35
  rectangle: 42.32,6.89 56.1,40.35
  rectangle: 62.01,6.89 75.79,40.35
  rectangle: 81.69,6.89 95.47,40.35
  rectangle: 101.38,6.89 115.16,40.35
Mechanical 16:
  lines w8: -198.82,-157.48 -198.82,23.62 ; -127.95,23.62 127.95,23.62 ; 198.82,-157.48 198.82,23.62
  lines w19.69: -236.22,-55.12 -204.72,-55.12 -204.72,-9.84 -236.22,-9.84 ; 236.22,-55.12 204.72,-55.12 204.72,-9.84 236.22,-9.84

## 52746-13 [mil]
pads (13):
  rect 11.81x31.5 smd: 1(-118.11,23.62) 2(-98.43,23.62) 3(-78.74,23.62) 4(-59.06,23.62) 5(-39.37,23.62) 6(-19.69,23.62) 7(0,23.62) 8(19.69,23.62) 9(39.37,23.62) 10(59.06,23.62) 11(78.74,23.62) 12(98.43,23.62) 13(118.11,23.62)
Top Layer:
  rectangle: -261.81,-78.74 -167.32,7.87
  rectangle: -218.5,-112.2 -167.32,-78.74
  rectangle: 167.32,-78.74 261.81,7.87
  rectangle: 167.32,-112.2 218.5,-78.74
Top Overlay:
  lines w8: -208.66,-157.48 -181.1,-157.48 -181.1,-196.85 -244.09,-196.85 -244.09,-204.72 ccw(c-228.34,-204.72) -228.35,-220.47 228.35,-220.47 ccw(c228.34,-204.72) 244.09,-204.72 244.09,-196.85 181.1,-196.85 181.1,-157.48 208.66,-157.48 ; -208.66,23.62 -137.8,23.62 ; 137.8,23.62 208.66,23.62
Top Paste:
  rectangle: -256.89,-74.8 -171.26,2.95
  rectangle: -214.57,-108.27 -171.26,-74.8
  rectangle: 171.26,-74.8 256.89,2.95
  rectangle: 171.26,-108.27 214.57,-74.8
Top Solder:
  rectangle: -261.81,-78.74 -167.32,7.87
  rectangle: -218.5,-112.2 -167.32,-78.74
  rectangle: 167.32,-78.74 261.81,7.87
  rectangle: 167.32,-112.2 218.5,-78.74
  rectangle: -125,6.89 -111.22,40.35
  rectangle: -105.32,6.89 -91.54,40.35
  rectangle: -85.63,6.89 -71.85,40.35
  rectangle: -65.94,6.89 -52.17,40.35
  rectangle: -46.26,6.89 -32.48,40.35
  rectangle: -26.57,6.89 -12.8,40.35
  rectangle: -6.89,6.89 6.89,40.35
  rectangle: 12.8,6.89 26.57,40.35
  rectangle: 32.48,6.89 46.26,40.35
  rectangle: 52.17,6.89 65.94,40.35
  rectangle: 71.85,6.89 85.63,40.35
  rectangle: 91.54,6.89 105.32,40.35
  rectangle: 111.22,6.89 125,40.35
Mechanical 16:
  lines w8: -208.66,-157.48 -208.66,23.62 ; -137.8,23.62 137.8,23.62 ; 208.66,-157.48 208.66,23.62
  lines w19.69: -246.06,-55.12 -214.57,-55.12 -214.57,-9.84 -246.06,-9.84 ; 246.06,-55.12 214.57,-55.12 214.57,-9.84 246.06,-9.84

## 52746-14 [mil]
pads (14):
  rect 11.81x31.5 smd: 1(-127.95,23.62) 2(-108.27,23.62) 3(-88.58,23.62) 4(-68.9,23.62) 5(-49.21,23.62) 6(-29.53,23.62) 7(-9.84,23.62) 8(9.84,23.62) 9(29.53,23.62) 10(49.21,23.62) 11(68.9,23.62) 12(88.58,23.62) 13(108.27,23.62) 14(127.95,23.62)
Top Layer:
  rectangle: -271.65,-78.74 -177.17,7.87
  rectangle: -228.35,-112.2 -177.17,-78.74
  rectangle: 177.17,-78.74 271.65,7.87
  rectangle: 177.17,-112.2 228.35,-78.74
Top Overlay:
  lines w8: -218.5,-157.48 -190.94,-157.48 -190.94,-196.85 -253.94,-196.85 -253.94,-204.72 ccw(c-238.19,-204.72) -238.19,-220.47 238.19,-220.47 ccw(c238.19,-204.72) 253.94,-204.72 253.94,-196.85 190.94,-196.85 190.94,-157.48 218.5,-157.48 ; -218.5,23.62 -147.64,23.62 ; 147.64,23.62 218.5,23.62
Top Paste:
  rectangle: -266.73,-74.8 -181.1,2.95
  rectangle: -224.41,-108.27 -181.1,-74.8
  rectangle: 181.1,-74.8 266.73,2.95
  rectangle: 181.1,-108.27 224.41,-74.8
Top Solder:
  rectangle: -271.65,-78.74 -177.17,7.87
  rectangle: -228.35,-112.2 -177.17,-78.74
  rectangle: 177.17,-78.74 271.65,7.87
  rectangle: 177.17,-112.2 228.35,-78.74
  rectangle: -134.84,6.89 -121.06,40.35
  rectangle: -115.16,6.89 -101.38,40.35
  rectangle: -95.47,6.89 -81.69,40.35
  rectangle: -75.79,6.89 -62.01,40.35
  rectangle: -56.1,6.89 -42.32,40.35
  rectangle: -36.42,6.89 -22.64,40.35
  rectangle: -16.73,6.89 -2.95,40.35
  rectangle: 2.95,6.89 16.73,40.35
  rectangle: 22.64,6.89 36.42,40.35
  rectangle: 42.32,6.89 56.1,40.35
  rectangle: 62.01,6.89 75.79,40.35
  rectangle: 81.69,6.89 95.47,40.35
  rectangle: 101.38,6.89 115.16,40.35
  rectangle: 121.06,6.89 134.84,40.35
Mechanical 16:
  lines w8: -218.5,-157.48 -218.5,23.62 ; -147.64,23.62 147.64,23.62 ; 218.5,-157.48 218.5,23.62
  lines w19.69: -255.91,-55.12 -224.41,-55.12 -224.41,-9.84 -255.91,-9.84 ; 255.91,-55.12 224.41,-55.12 224.41,-9.84 255.91,-9.84

## 52746-15 [mil]
pads (15):
  rect 11.81x31.5 smd: 1(-137.8,23.62) 2(-118.11,23.62) 3(-98.43,23.62) 4(-78.74,23.62) 5(-59.06,23.62) 6(-39.37,23.62) 7(-19.69,23.62) 8(0,23.62) 9(19.69,23.62) 10(39.37,23.62) 11(59.06,23.62) 12(78.74,23.62) 13(98.43,23.62) 14(118.11,23.62) 15(137.8,23.62)
Top Layer:
  rectangle: -281.5,-78.74 -187.01,7.87
  rectangle: -238.19,-112.2 -187.01,-78.74
  rectangle: 187.01,-78.74 281.5,7.87
  rectangle: 187.01,-112.2 238.19,-78.74
Top Overlay:
  lines w8: -228.35,-157.48 -200.79,-157.48 -200.79,-196.85 -263.78,-196.85 -263.78,-204.72 ccw(c-248.03,-204.72) -248.03,-220.47 248.03,-220.47 ccw(c248.03,-204.72) 263.78,-204.72 263.78,-196.85 200.79,-196.85 200.79,-157.48 228.35,-157.48 ; -228.35,23.62 -157.48,23.62 ; 157.48,23.62 228.35,23.62
Top Paste:
  rectangle: -276.57,-74.8 -190.94,2.95
  rectangle: -234.25,-108.27 -190.94,-74.8
  rectangle: 190.94,-74.8 276.57,2.95
  rectangle: 190.94,-108.27 234.25,-74.8
Top Solder:
  rectangle: -281.5,-78.74 -187.01,7.87
  rectangle: -238.19,-112.2 -187.01,-78.74
  rectangle: 187.01,-78.74 281.5,7.87
  rectangle: 187.01,-112.2 238.19,-78.74
  rectangle: -144.69,6.89 -130.91,40.35
  rectangle: -125,6.89 -111.22,40.35
  rectangle: -105.32,6.89 -91.54,40.35
  rectangle: -85.63,6.89 -71.85,40.35
  rectangle: -65.94,6.89 -52.17,40.35
  rectangle: -46.26,6.89 -32.48,40.35
  rectangle: -26.57,6.89 -12.8,40.35
  rectangle: -6.89,6.89 6.89,40.35
  rectangle: 12.8,6.89 26.57,40.35
  rectangle: 32.48,6.89 46.26,40.35
  rectangle: 52.17,6.89 65.94,40.35
  rectangle: 71.85,6.89 85.63,40.35
  rectangle: 91.54,6.89 105.32,40.35
  rectangle: 111.22,6.89 125,40.35
  rectangle: 130.91,6.89 144.69,40.35
Mechanical 16:
  lines w8: -228.35,-157.48 -228.35,23.62 ; -157.48,23.62 157.48,23.62 ; 228.35,-157.48 228.35,23.62
  lines w19.69: -265.75,-55.12 -234.25,-55.12 -234.25,-9.84 -265.75,-9.84 ; 265.75,-55.12 234.25,-55.12 234.25,-9.84 265.75,-9.84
